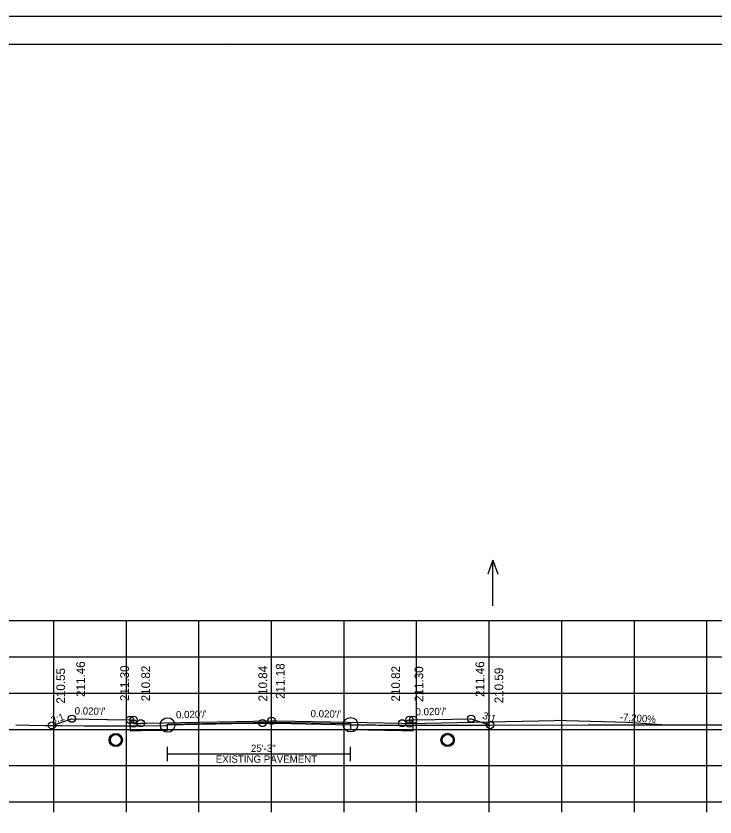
# Model space of a CAD drawing. Extents: x 1368968 to 1369915, y 377395 to 380381.
# Drawn here: x 1369102.9 to 1369199.2, y 377723.9 to 377834.4 of the extents above; entities that cross this region are included whole.
import ezdxf

# ---------------------------------------------------------------- set-up
doc = ezdxf.new("R2010")
doc.units = 0
for name, color, linetype in [('Default', 7, 'Continuous'), ('S_BORDER_NO_PLOT', 7, 'Continuous'), ('S_BREAKLINE_ANNOT', 7, 'Continuous'), ('S_BRIDGE_ANNOT', 7, 'Continuous'), ('S_CROSS_DRAIN', 7, 'Continuous'), ('S_CTL_TABLE', 7, 'Continuous'), ('S_CURB_ANNOT', 7, 'Continuous'), ('S_DITCHLINE_ANNOT', 7, 'Continuous'), ('S_DROP_INLET', 7, 'Continuous'), ('S_EXIST_ROW_ANNOT', 7, 'Continuous'), ('S_EXISTING_ALIGNMENT', 7, 'Continuous'), ('S_EXISTING_ALIGNMENT_ANNOT', 7, 'Continuous'), ('S_FENCE', 7, 'Continuous')]:
    doc.layers.add(name, color=color, linetype=linetype)

msp = doc.modelspace()

# ---------------------------------------------------------------- linework, layer by layer
at = {"layer": 'Default'}
msp.add_line((1369149.02, 377736.81), (1369149.02, 377735.98), dxfattribs=at)
at = {"layer": 'S_BORDER_NO_PLOT'}
msp.add_lwpolyline([(1369118.62, 377737.31), (1369118.63, 377735.8), (1369120.13, 377735.83), (1369123.81, 377735.9), (1369123.81, 377736.74), (1369138.13, 377737.02), (1369149.02, 377736.81), (1369149.02, 377735.98), (1369156.13, 377735.83), (1369157.63, 377735.8), (1369157.64, 377737.31)], dxfattribs=at)
at = {"layer": 'S_BREAKLINE_ANNOT'}
for p, q in [((1368998.13, 377726.01), (1369278.13, 377726.01)), ((1369108.13, 377724.61), (1369108.13, 377726.01)), ((1369118.13, 377724.61), (1369118.13, 377726.01)), ((1369128.13, 377724.61), (1369128.13, 377726.01)), ((1369138.13, 377724.61), (1369138.13, 377726.01)), ((1369148.13, 377724.61), (1369148.13, 377726.01)), ((1369158.13, 377724.61), (1369158.13, 377726.01)), ((1369168.13, 377724.61), (1369168.13, 377726.01)), ((1369178.13, 377724.61), (1369178.13, 377726.01)), ((1369188.13, 377724.61), (1369188.13, 377726.01)), ((1369198.13, 377724.61), (1369198.13, 377726.01))]:
    msp.add_line(p, q, dxfattribs=at)
at = {"layer": 'S_BRIDGE_ANNOT'}
for p, q in [((1368980.13, 377830.47), (1369296.31, 377830.47)), ((1369132.65, 377830.21), (1369132.65, 377830.21)), ((1369132.65, 377830.21), (1369132.65, 377830.21))]:
    msp.add_line(p, q, dxfattribs=at)
at = {"layer": 'S_CROSS_DRAIN'}
for p, q in [((1369157.13, 377736.82), (1369177.13, 377737.21)), ((1369187.12, 377736.96), (1369177.13, 377737.21)), ((1369191.87, 377736.61), (1369187.12, 377736.96)), ((1369123.81, 377732.61), (1369149.02, 377732.61))]:
    msp.add_line(p, q, dxfattribs=at)
at = {"layer": 'S_CTL_TABLE'}
msp.add_lwpolyline([(1369102.88, 377736.63), (1369104.73, 377736.6), (1369106.89, 377736.56), (1369109.18, 377736.52), (1369112.31, 377736.5), (1369112.59, 377736.5), (1369112.69, 377736.5), (1369115.75, 377736.51), (1369119.94, 377736.5), (1369123.58, 377736.53), (1369123.81, 377736.61), (1369132.64, 377736.8), (1369136.88, 377736.88), (1369140.89, 377736.8), (1369149.02, 377736.65), (1369152.5, 377736.61), (1369152.85, 377736.6), (1369152.95, 377736.6), (1369153, 377736.6), (1369166.61, 377736.6), (1369166.7, 377736.6), (1369168.23, 377736.6), (1369181.75, 377736.61), (1369194.75, 377736.61), (1369197.18, 377736.62), (1369210.06, 377736.62)], dxfattribs=at)
at = {"layer": 'S_CURB_ANNOT'}
msp.add_lwpolyline([(1369107.88, 377736.56), (1369110.57, 377737.46), (1369110.62, 377737.48), (1369115.42, 377737.38), (1369115.62, 377737.38), (1369118.5, 377737.32), (1369118.62, 377737.32), (1369118.64, 377737.32), (1369119.12, 377737.32), (1369119.13, 377736.84), (1369119.13, 377736.82), (1369120.09, 377736.83), (1369120.13, 377736.84), (1369120.85, 377736.85), (1369138.13, 377737.2), (1369138.85, 377737.18), (1369156.13, 377736.84), (1369157.09, 377736.82), (1369157.13, 377736.82), (1369157.13, 377736.84), (1369157.14, 377737.32), (1369157.62, 377737.32), (1369157.64, 377737.32), (1369157.76, 377737.32), (1369160.64, 377737.38), (1369165.44, 377737.47), (1369165.64, 377737.48), (1369168.13, 377736.65), (1369168.26, 377736.6)], dxfattribs=at)
at = {"layer": 'S_DITCHLINE_ANNOT'}
for p, q in [((1368998.13, 377751.01), (1369278.13, 377751.01)), ((1369108.13, 377726.01), (1369108.13, 377751.01)), ((1369118.13, 377726.01), (1369118.13, 377751.01)), ((1369128.13, 377726.01), (1369128.13, 377751.01)), ((1369138.13, 377726.01), (1369138.13, 377751.01)), ((1369148.13, 377726.01), (1369148.13, 377751.01)), ((1369158.13, 377726.01), (1369158.13, 377751.01)), ((1369168.13, 377726.01), (1369168.13, 377751.01)), ((1369178.13, 377726.01), (1369178.13, 377751.01)), ((1369188.13, 377726.01), (1369188.13, 377751.01)), ((1369198.13, 377726.01), (1369198.13, 377751.01)), ((1368998.13, 377746.01), (1369278.13, 377746.01)), ((1368998.13, 377741.01), (1369278.13, 377741.01)), ((1368998.13, 377736.01), (1369278.13, 377736.01)), ((1368998.13, 377731.01), (1369278.13, 377731.01)), ((1368998.13, 377726.01), (1369278.13, 377726.01))]:
    msp.add_line(p, q, dxfattribs=at)
at = {"layer": 'S_DROP_INLET'}
msp.add_line((1368967.73, 377834.37), (1369301.07, 377834.37), dxfattribs=at)
for points in [[(1368967.73, 377834.37), (1369301.07, 377834.37), (1369301.07, 377621.03), (1368967.73, 377621.03)], [(1369214.05, 377830.47), (1369214.05, 377820.59), (1369249.79, 377820.59), (1369249.79, 377817.67), (1369272.99, 377817.67), (1369272.99, 377793.34), (1369296.31, 377793.34), (1369296.31, 377625.01), (1368980.13, 377625.01), (1368980.13, 377830.47)]]:
    msp.add_lwpolyline(points, close=True, dxfattribs=at)
for centre, radius in [((1369107.88, 377736.56), 0.5), ((1369110.62, 377737.48), 0.5), ((1369118.62, 377737.32), 0.5), ((1369119.12, 377737.32), 0.5), ((1369119.13, 377736.82), 0.5), ((1369120.13, 377736.84), 0.5), ((1369120.13, 377736.84), 0.5), ((1369123.81, 377736.61), 1), ((1369136.88, 377736.88), 0.5), ((1369138.13, 377737.2), 0.5), ((1369149.02, 377736.65), 1), ((1369156.13, 377736.84), 0.5), ((1369156.13, 377736.84), 0.5), ((1369157.13, 377736.82), 0.5), ((1369157.14, 377737.32), 0.5), ((1369157.64, 377737.32), 0.5), ((1369165.64, 377737.48), 0.5), ((1369168.26, 377736.6), 0.5), ((1369116.67, 377734.54), 0.917), ((1369162.4, 377734.55), 0.917)]:
    msp.add_circle(centre, radius, dxfattribs=at)
at = {"layer": 'S_EXIST_ROW_ANNOT'}
for p, q in [((1369123.81, 377731.61), (1369123.81, 377733.61)), ((1369149.02, 377731.61), (1369149.02, 377733.61))]:
    msp.add_line(p, q, dxfattribs=at)
for centre in [(1369116.67, 377734.54), (1369162.4, 377734.55)]:
    msp.add_circle(centre, 0.75, dxfattribs=at)
at = {"layer": 'S_EXISTING_ALIGNMENT'}
for p, q in [((1369168.63, 377759.34), (1369167.93, 377757.42)), ((1369168.63, 377753.06), (1369168.63, 377759.34)), ((1369168.63, 377759.34), (1369169.33, 377757.42))]:
    msp.add_line(p, q, dxfattribs=at)
at = {"layer": 'S_EXISTING_ALIGNMENT_ANNOT'}
msp.add_line((1369138.13, 377736.86), (1369138.13, 377746.86), dxfattribs=at)

# ---------------------------------------------------------------- texts
at = {"layer": 'S_CROSS_DRAIN'}
msp.add_text('-7.200%', height=1, rotation=355.8818, dxfattribs=at).set_placement((1369186.09, 377737.23))
at = {"layer": 'S_EXIST_ROW_ANNOT'}
for s, p in [('25\'-3"', (1369135.29, 377732.9)), ('EXISTING PAVEMENT', (1369130.45, 377731.41))]:
    msp.add_text(s, height=1, dxfattribs=at).set_placement(p)
at = {"layer": 'S_EXISTING_ALIGNMENT_ANNOT'}
for s, p in [('211.46', (1369112.42, 377740.48)), ('211.30', (1369118.48, 377739.91)), ('210.82', (1369121.39, 377739.88)), ('210.84', (1369137.53, 377739.86)), ('211.18', (1369139.93, 377740.2)), ('210.82', (1369155.84, 377739.84)), ('211.46', (1369167.44, 377740.48)), ('210.55', (1369109.68, 377739.56)), ('211.30', (1369159.04, 377739.79)), ('210.59', (1369170.06, 377739.6))]:
    msp.add_text(s, height=1.2, rotation=90, dxfattribs=at).set_placement(p)
at = {"layer": 'S_FENCE'}
for s, rotation, p in [('3:1', 18.4324, (1369107.91, 377736.74)), ("0.020'/'", 358.8543, (1369110.99, 377738.07)), ("0.020'/'", 1.1458, (1369124.97, 377737.53)), ("0.020'/'", 358.8543, (1369143.5, 377737.69)), ("0.020'/'", 1.1457, (1369157.98, 377737.92)), ('3:1', 341.5608, (1369167.11, 377737.51))]:
    msp.add_text(s, height=1, rotation=rotation, dxfattribs=at).set_placement(p)

doc.saveas('drawing.dxf')
